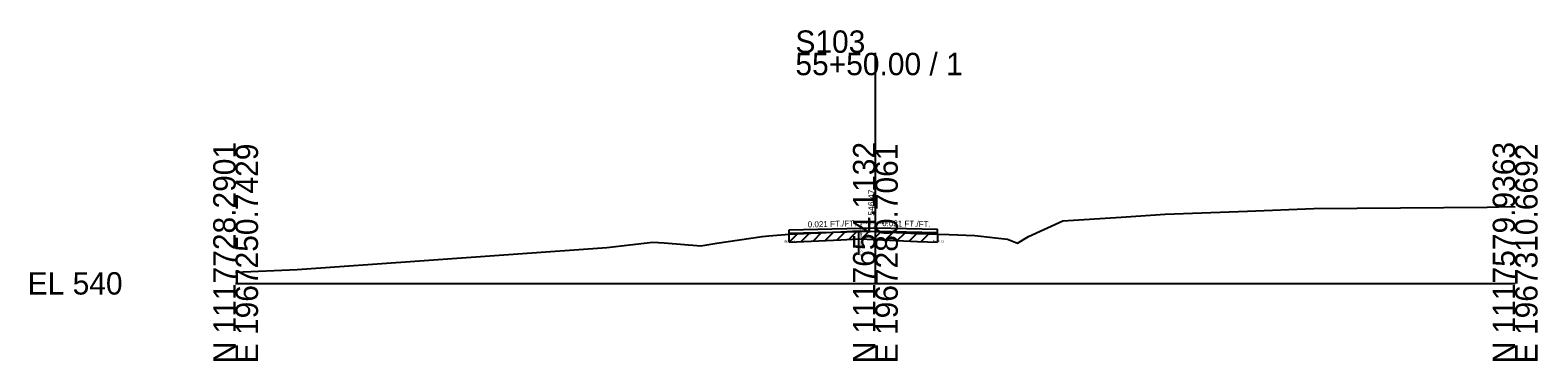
# Model space of a CAD drawing. Extents: x -26 to 163, y -10 to 24018.
# Drawn here: x -25.7 to 162.8, y 4990.3 to 5031.7 of the extents above; entities that cross this region are included whole.
import ezdxf

# ---------------------------------------------------------------- set-up
doc = ezdxf.new("R2010")
doc.units = 0
for name, color, linetype in [('RD_GPK_XS_Cell', 7, 'Continuous'), ('RD_XS_ExGround', 7, 'Continuous'), ('RD_XS_ExPaveRet', 7, 'Continuous'), ('RD_XS_Misc_Line', 7, 'Continuous'), ('RD_XS_PaveOvlay_CP', 7, 'Continuous'), ('RD_XS_TX_Elev_EX', 7, 'Continuous'), ('RD_XS_TX_ExEOP', 7, 'Continuous'), ('RD_XS_TX_Notes', 7, 'Continuous'), ('RD_XS_TX_Profile', 7, 'Continuous'), ('RD_XS_TX_Slope', 7, 'Continuous')]:
    doc.layers.add(name, color=color, linetype=linetype)

msp = doc.modelspace()

# ---------------------------------------------------------------- linework, layer by layer
at = {"layer": 'RD_GPK_XS_Cell'}
for p, q in [((80, 5000), (80, 5028.84)), ((0, 5000), (80, 5000)), ((80, 5000), (160, 5000))]:
    msp.add_line(p, q, dxfattribs=at)
at = {"layer": 'RD_XS_ExGround'}
msp.add_lwpolyline([(0, 5001.42), (7.7, 5001.74), (23.01, 5002.81), (46.41, 5004.49), (52.19, 5005.15), (53.59, 5005.06), (58.18, 5004.69), (60.16, 5005.02), (65.84, 5005.86), (66.67, 5005.94), (69.23, 5006.15), (75.68, 5006.46), (77.87, 5006.56), (80, 5006.47), (85.26, 5006.23), (87.77, 5006.15), (89.22, 5006.12), (92.43, 5005.99), (96.52, 5005.54), (97.78, 5005.01), (99.16, 5005.87), (103.45, 5007.83), (110.74, 5008.28), (116.23, 5008.66), (126.52, 5009.04), (134.83, 5009.36), (156.52, 5009.55), (159.34, 5009.61), (160, 5009.58)], dxfattribs=at)
at = {"layer": 'RD_XS_ExPaveRet'}
for p, q in [((69.23, 5005.15), (70.28, 5006.2)), ((69.23, 5005.15), (69.23, 5006.15)), ((70.73, 5005.22), (71.78, 5006.27)), ((72.23, 5005.29), (73.28, 5006.35)), ((73.73, 5005.37), (74.78, 5006.42)), ((75.23, 5005.44), (76.27, 5006.49)), ((75.68, 5005.46), (77.87, 5005.56)), ((76.73, 5005.51), (77.77, 5006.56)), ((77.87, 5005.56), (80, 5005.47)), ((78.23, 5005.55), (79.18, 5006.5)), ((79.73, 5005.48), (80.68, 5006.44)), ((81.23, 5005.41), (82.18, 5006.37)), ((82.73, 5005.35), (83.68, 5006.3)), ((84.23, 5005.28), (85.18, 5006.24)), ((85.73, 5005.22), (86.69, 5006.19)), ((87.77, 5006.15), (87.77, 5005.15)), ((69.23, 5005.15), (75.68, 5005.46)), ((80, 5005.47), (85.26, 5005.23)), ((85.26, 5005.23), (87.77, 5005.15))]:
    msp.add_line(p, q, dxfattribs=at)
at = {"layer": 'RD_XS_Misc_Line'}
msp.add_line((77.87, 5006.56), (77.87, 5003.56), dxfattribs=at)
at = {"layer": 'RD_XS_PaveOvlay_CP'}
for p, q in [((69.23, 5006.7), (80, 5006.93)), ((69.23, 5006.15), (69.23, 5006.7)), ((80, 5006.47), (69.23, 5006.24)), ((80, 5006.93), (87.77, 5006.77)), ((87.77, 5006.31), (80, 5006.47)), ((87.77, 5006.15), (87.77, 5006.77))]:
    msp.add_line(p, q, dxfattribs=at)

# ---------------------------------------------------------------- texts
at = {"layer": 'RD_GPK_XS_Cell'}
for s, p in [('S103', (70, 5028.84)), ('55+50.00 / 1', (70, 5026.04)), ('EL 540', (-26, 4998.6))]:
    msp.add_text(s, height=2.8, dxfattribs=at).set_placement(p)
for s, p in [('N 1117728.2901', (0, 4990)), ('E 1967250.7429', (2.8, 4990)), ('N 1117654.1132', (80, 4990)), ('E 1967280.7061', (82.8, 4990)), ('N 1117579.9363', (160, 4990)), ('E 1967310.6692', (162.8, 4990))]:
    msp.add_text(s, height=2.8, rotation=90, dxfattribs=at).set_placement(p)
at = {"layer": 'RD_XS_TX_Elev_EX'}
msp.add_text('546.47', height=0.8, rotation=90, dxfattribs=at).set_placement((79.9, 5008.47))
at = {"layer": 'RD_XS_TX_ExEOP'}
for s, p in [('EOP-L', (69.18, 5006.7)), ('EOP-R', (87.72, 5006.77))]:
    msp.add_text(s, height=0.1, rotation=270, dxfattribs=at).set_placement(p)
at = {"layer": 'RD_XS_TX_Notes'}
msp.add_text(' Min. Distance @CP = -0.14', height=0.25, rotation=270, dxfattribs=at).set_placement((78.12, 5007.66))
for s, p in [('Elev. @CL = 546.93', (78.48, 5007.43)), (' dE= 0.46', (79.29, 5005.47)), (' dE= 0.56', (68.51, 5005.15)), (' dE= 0.61', (87.07, 5005.15))]:
    msp.add_text(s, height=0.25, dxfattribs=at).set_placement(p)
at = {"layer": 'RD_XS_TX_Profile'}
msp.add_text('CL', height=0.25, dxfattribs=at).set_placement((79.77, 5006.93))
at = {"layer": 'RD_XS_TX_Slope'}
for rotation, p in [(1.1916, (71.55, 5007)), (358.8084, (80.84, 5007.16))]:
    msp.add_text('0.021 FT./FT.', height=0.75, rotation=rotation, dxfattribs=at).set_placement(p)

doc.saveas('drawing.dxf')
